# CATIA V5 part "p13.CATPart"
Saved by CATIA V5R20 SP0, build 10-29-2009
Part number: p13
Bounding box of the stored display mesh (mm): x -10 to -5, y -55 to -45, z -4.991 to 64.991
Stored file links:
  D:\Dropbox\IAO_2011\MMS_GR2\IAO_2011_1439_jlicbarski\p13.CATPart
  D:\Dropbox\IAO_2011\MMS_GR2\IAO_2011_1439_jlicbarski\train.CATProduct
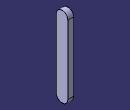
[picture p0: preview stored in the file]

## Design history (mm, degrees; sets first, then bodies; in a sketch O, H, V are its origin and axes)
AxisSystem1: origin (0, 0, 0), X (1, 0, 0), Y (0, 1, 0), Z (0, 0, 1)
Set1
  Plane1: linked copy from another document
  Line1: linked copy from another document
  Line2: linked copy from another document
Body1 (main body)
  Sketch1 on Plane1, origin (-5, 0, 0), H (0, 1, 0), V (0, 0, 1)
    arc A1 centre (-50, 60) radius 5 from (-45, 60) to (-55, 60.0208) ccw
    reference projected point E1 (-50, 60) from Line1
    arc A2 centre (-50, 0) radius 5 from (-54.9999, -0.029) to (-45, 0) ccw
    reference projected point E2 (-50, 0) from Line2
    line L1 (-45, 60) -> (-45, 0)
    line L2 (-55, 60.0208) -> (-54.9999, -0.029)
    radius A1 = 5
    distance A1 E1 = 5
    radius A2 = 5
    distance A2 E2 = 5
  Pad1: profile Sketch1, direction (-1, 0, 0), length 5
